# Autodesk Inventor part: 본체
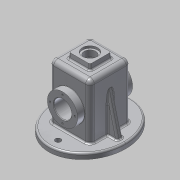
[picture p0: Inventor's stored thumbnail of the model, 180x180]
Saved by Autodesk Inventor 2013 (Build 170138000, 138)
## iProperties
Created: 2017-07
Part Number: 본체
Material: 알루미늄 6061
Document SubType Name: Modeling
Designer: Administrator
Density: 2.71 g/cm^3
Mass: 894.996 g
Surface Area: 993.064 cm^2
Volume: 330.257 cm^3
Author: Administrator
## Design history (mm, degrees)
sketch "스케치2"
  geometry: L1 (0, 0)-(74, 0); L2 (74, 0)-(74, 110); L3 (74, 110)-(0, 110); L4 (0, 110)-(0, 0)
  constraints: 8 end point, 2 parallel, 1 horizontal, 1 perpendicular
  dimensions: "d2" = 74 distance of L2.end L3.end; "d4" = 110 distance of L1.end L2.end
extrude "돌출1" new body sketch "스케치2" distance "d5" = 74; taper "d6" = 0 deg
feature "쉘1" dims "d7" = 5
sketch "스케치3" dims "d8" = 65, "d10" = 75
  geometry: L1 (5, 5)-(5, 69) reference; L2 (5, 69)-(69, 69) reference; L3 (69, 69)-(69, 5) reference; L4 (69, 5)-(5, 5) reference; L5 (0, 0)-(0, 74) reference; L6 (0, 0)-(74, 0) reference; L7 (74, 74)-(74, 0) reference; L8 (0, 74)-(74, 74) reference; L9 (37, 0)-(37, 74); L10 (74, 37)-(0, 37); 1 further point; 1 other entity
  constraints: 4 end point, 4 midpoint, 1 vertical, 2 other
  dimensions: "d11" = 0 distance from line of L9 point (37, 37); "d12" = 0 distance from line of L10 point (37, 37)
extrude "돌출2" join sketch "스케치3" distance "d13" = 10; taper "d14" = 0 deg
fillet "모깎기1" dims "d15" = 8, "d16" = 3
sketch "스케치4"
  geometry: L1 (0, -89)-(0, 0) reference; L2 (94, -102)-(-36, -102) reference; C1 r 27.5 at (29, -47); 1 further point
  constraints: 1 centre point
  dimensions: "d17" = 55 distance from line of L2 C1.centre; "d18" = 29 distance from line of C1.centre L1; "d19" = 55 diameter of C1
extrude "돌출3" join sketch "스케치4" distance "d20" = 13; taper "d21" = 0 deg
sketch "스케치5"
  geometry: L1 (58, 0)-(58, -89) reference; L2 (-36, 13)-(94, 13) reference; C1 r 27.5 at (29, -42); 1 further point
  constraints: 1 centre point
  dimensions: "d22" = 55 distance from line of L2 C1.centre; "d23" = 55 diameter of C1; "d24" = 29 distance from line of L1 C1.centre
extrude "돌출4" join sketch "스케치5" distance "d25" = 13; taper "d26" = 0 deg
sketch "스케치6"
  geometry: L1 (58, 0)-(58, -102) reference; L2 (0, 0)-(58, 0) reference; C1 r 27.5 at (29, -55); 1 further point
  constraints: 1 centre point
  dimensions: "d27" = 55 distance from line of L2 C1.centre; "d28" = 29 distance from line of L1 C1.centre; "d29" = 55 diameter of C1
extrude "돌출5" join sketch "스케치6" distance "d30" = 7; taper "d31" = -45 deg
sketch "스케치7"
  geometry: L1 (58, 0)-(58, -102) reference; L2 (58, -102)-(0, -102) reference; C1 r 27.5 at (29, -47); 1 further point
  constraints: 1 centre point
  dimensions: "d32" = 55 distance from line of L2 C1.centre; "d33" = 29 distance from line of L1 C1.centre; "d34" = 55 diameter of C1
extrude "돌출6" join sketch "스케치7" distance "d35" = 7; taper "d36" = -45 deg
sketch "스케치8"
  geometry: C1 r 27.5 at (0, 0) reference; C2 r 16 at (0, 0); 1 further point
  constraints: 1 centre point, 1 coincident
  dimensions: "d37" = 32 diameter of C2
extrude "돌출7" cut sketch "스케치8" stored distance "d39" = 7; taper "d40" = 0 deg
sketch "스케치9"
  geometry: C1 r 5 at (-37, -21); C2 r 5 at (-37, 95); 2 further points; 1 other entity
  constraints: 2 centre point, 1 other
  dimensions: "d41" = 0 horizontal distance of point (-37, 37) C1.centre; "d42" = 0 horizontal distance of C2.centre point (-37, 37); "d43" = 58 distance of point (-37, 37) C1.centre; "d44" = 58 distance of C2.centre point (-37, 37); "d45" = 10 diameter of C1; "d46" = 10 diameter of C2
extrude "돌출8" cut sketch "스케치9" stored distance "d47" = 7; taper "d48" = 0 deg
sketch "스케치10"
  geometry: L1 (0, -58)-(0, 0) reference; L2 (58, -58)-(0, -58) reference; L3 (9, -49)-(49, -49); L4 (49, -49)-(49, -9); L5 (49, -9)-(9, -9); L6 (9, -9)-(9, -49); 1 further point
  constraints: 8 end point, 2 parallel, 1 horizontal, 1 perpendicular
  dimensions: "d53" = 40 distance of L5.end L3.start; "d54" = 40 distance of L4.end L5.end; "d55" = 9 distance between parallel lines of L6 L1; "d56" = 9 distance between parallel lines of L2 L3
extrude "돌출9" join sketch "스케치10" distance "d57" = 10; taper "d58" = -5 deg
fillet "모깎기2" dims "d59" = 3
sketch "스케치11"
  geometry: L1 (0, -58)-(0, 0) reference; L2 (0, 0)-(58, 0) reference; C1 r 14 at (29, -29); 1 further point
  constraints: 1 centre point
  dimensions: "d60" = 29 distance from line of C1.centre L1; "d61" = 29 distance from line of C1.centre L2; "d62" = 28 diameter of C1
extrude "돌출10" cut sketch "스케치11" distance "d63" = 4; taper "d64" = 0 deg
sketch "스케치12"
  geometry: C1 r 14 at (0, 0) reference; C2 r 10.5 at (0, 0); 1 further point
  constraints: 1 centre point, 1 coincident
  dimensions: "d65" = 21 diameter of C2
extrude "돌출11" cut sketch "스케치12" stored distance "d67" = 4; taper "d68" = 0 deg
sketch "스케치13" dims "d69" = 45
  geometry: C1 r 16 at (0, 0) reference; C2 r 27.5 at (0, 0) reference; 3 further points
  constraints: 1 coincident, 1 vertical alignment, 2 other
  dimensions: "d71" = 0 horizontal distance of C1.centre point (0, 22.5)
hole "구멍1" sketch "스케치13" at (0, 22.5) diameter "d72" = 3.242; stored, may be unused: countersink angle "d76" = 90 deg, drill point angle "d78" = 118 deg; dims "d73" = 8, "d74" = 4, "d75" = 2, "d77" = 10
sketch "스케치14" dims "d82" = 45
  geometry: C1 r 16 at (0, 0) reference; C2 r 27.5 at (0, 0) reference; 3 further points
  constraints: 1 coincident, 1 vertical alignment, 2 other
  dimensions: "d84" = 0 horizontal distance of C1.centre point (0, -22.5)
hole "구멍2" sketch "스케치14" at (0, -22.5) diameter "d85" = 3.242; stored, may be unused: countersink angle "d89" = 90 deg, drill point angle "d91" = 118 deg; dims "d86" = 8, "d87" = 4, "d88" = 2, "d90" = 10
node "작업 평면2"
sketch "스케치15"
  geometry: L1 (94, -92)-(-36, -92) reference; L2 (-8, -89)-(-8, 0) reference; L3 (66, 0)-(66, -89) reference; L4 (-8, -19.806)-(-26, -92); L5 (66, -19.806)-(84, -92); L6 (94, -92)-(-36, -92) reference; L7 (94, -102)-(-36, -102) reference; L8 (-36, -92)-(-36, -57); 1 further point
  constraints: 6 end point, 4 point on line, 1 equal length, 1 perpendicular
  dimensions: "d95" = 10 distance of L1.start L5.end; "d96" = 10 distance of L1.end L4.end; "d111" = 14 deg angle of L4 L8
  node "투영된 루프1"
fillet "모깎기3" dims "d99" = 0.5
chamfer "모따기1" distance "d101" = 1; stored, may be unused: second distance "d102" = 2, angle "d103" = 45 deg
sketch "스케치16"
  geometry: L1 (0, 0)-(0, 89) reference; L2 (51.066, 7.438)-(6.934, 7.438); L3 (6.934, 7.438)-(6.934, 16.562); L4 (6.934, 16.562)-(51.066, 16.562); L5 (51.066, 16.562)-(51.066, 7.438); L6 (29, 7.438)-(29, 16.562); L7 (51.066, 12)-(6.934, 12); L8 (12.863, -18)-(45.137, -18) reference; 2 further points
  constraints: 4 end point, 4 midpoint, 2 other
  dimensions: "d104" = 30 distance between parallel lines of L7 L8; "d105" = 29 distance between parallel lines of L1 L6; "d106" = 44.1319 distance of L2.start L2.end; "d107" = 9.12397 distance of L2.end L3.end
feature "엠보싱1" sketch "스케치16" dims "d2" = 74, "d4" = 110, "d10" = 75, "d108" = 0.5, "d109" = 0
feature "리브1" dims "d112" = 1, "d113" = 10, "d114" = 0, "d115" = 0, "d116" = 1, "d117" = 1
sketch "스케치17"
  geometry: L1 (94, -92)-(-36, -92) reference; L2 (66, 0)-(66, -89) reference; L3 (84, -92)-(66, -19.806); L4 (94, -92)-(94, -53); 1 further point
  constraints: 4 end point, 2 point on line, 1 parallel
  dimensions: "d118" = 39 distance of L1.start L4.end; "d119" = 14 deg angle of L4 L3; "d120" = 10 distance of L1.start L3.start
feature "리브2" sketch "스케치17" dims "d121" = 1, "d122" = 10, "d123" = 0, "d124" = 0, "d125" = 1, "d126" = 1
fillet "모깎기4" dims "d127" = 3
fillet "모깎기5" dims "d128" = 3
node "솔리드1"
pattern_circular "원형 패턴1" dims angle "d80" = 360 deg
pattern_circular "원형 패턴2" dims angle "d93" = 360 deg
